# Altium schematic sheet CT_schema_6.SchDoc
size 370 x 245 mm
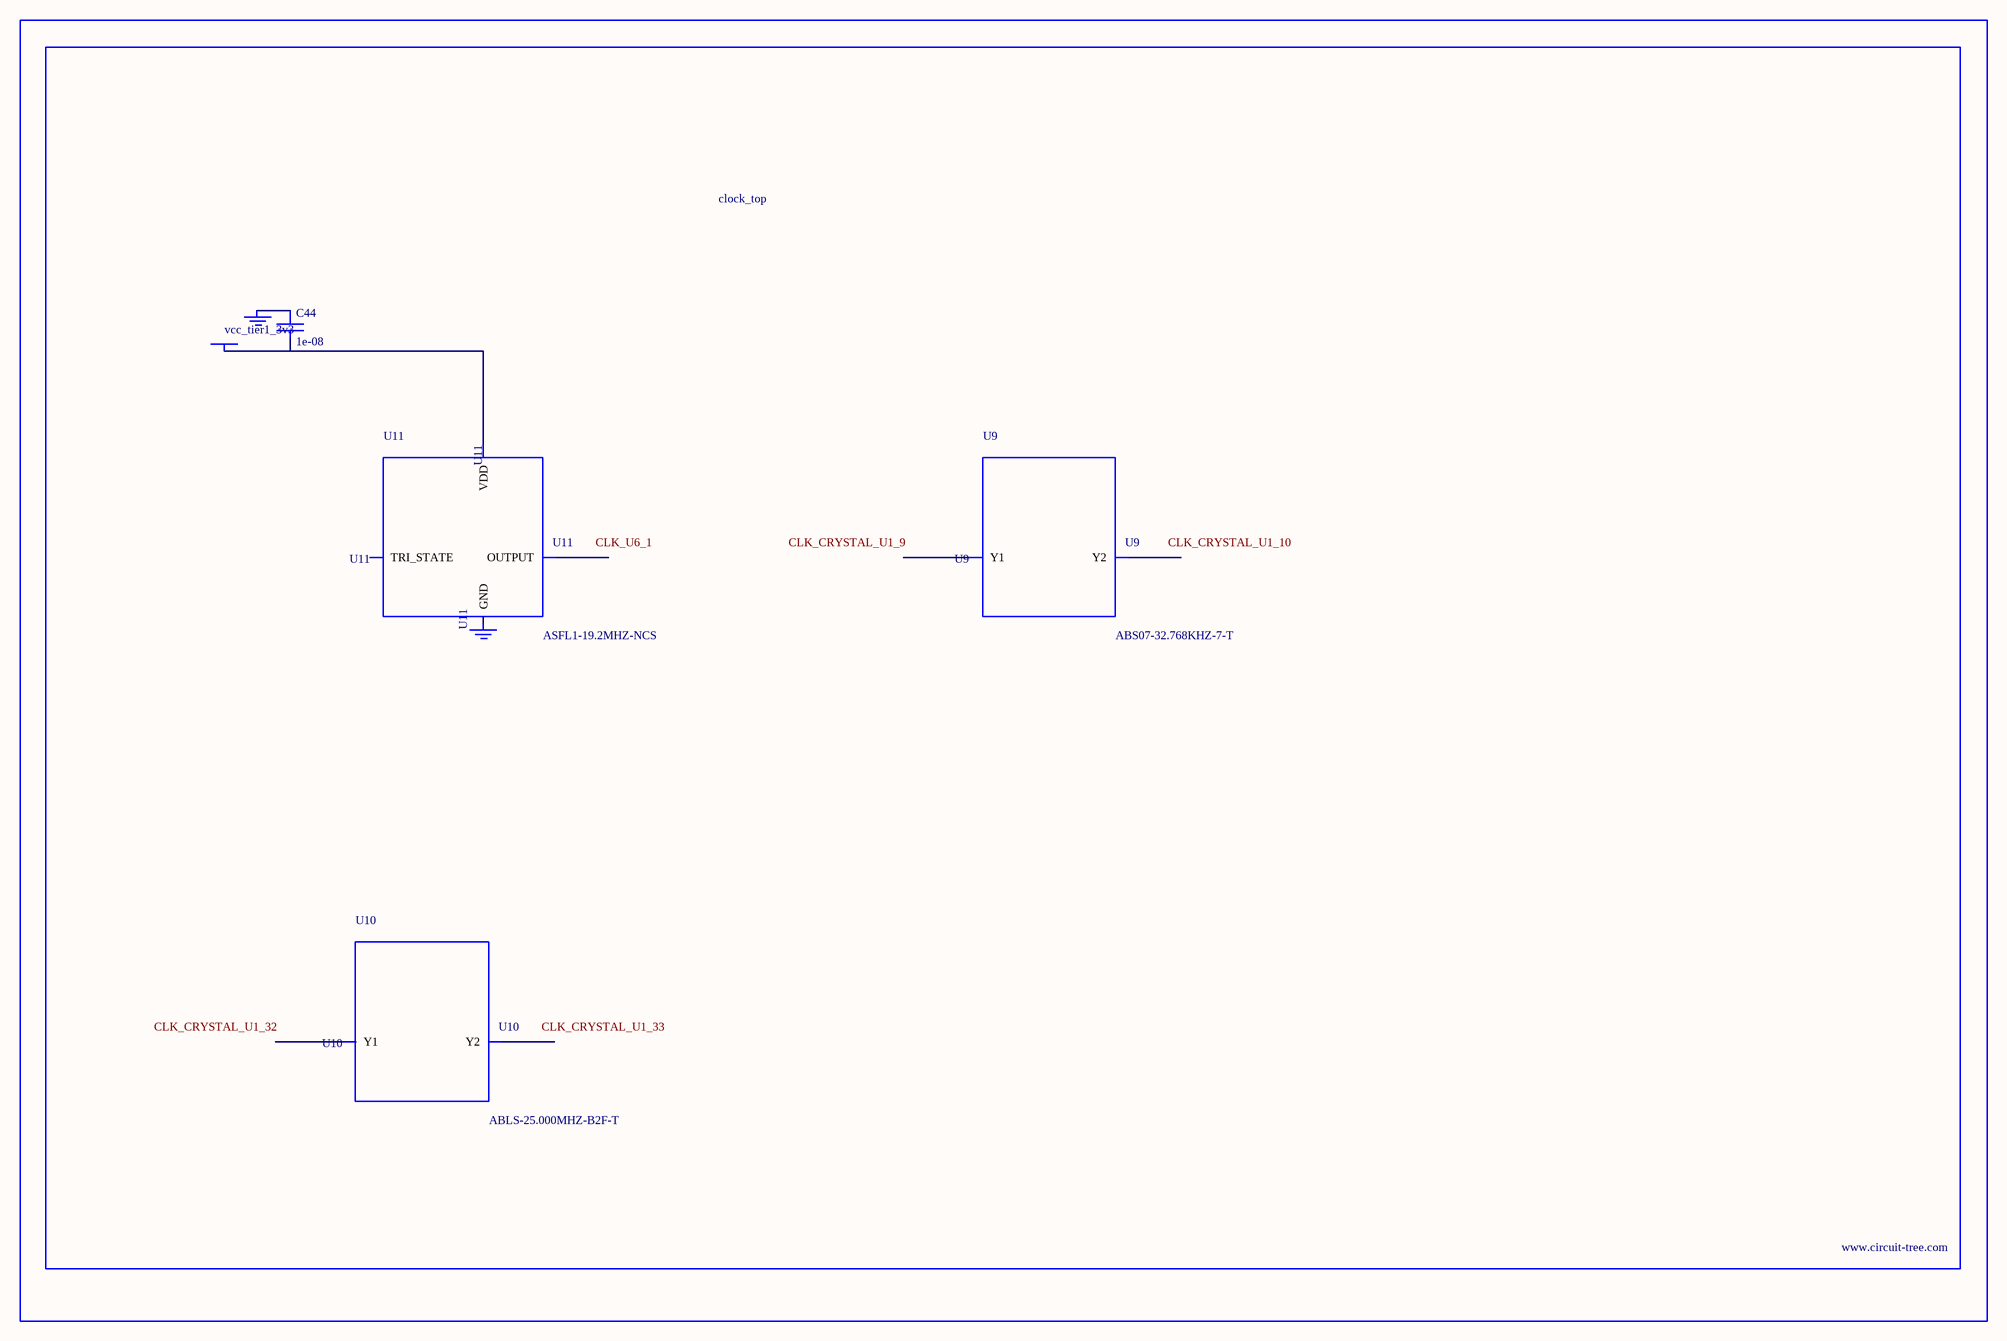
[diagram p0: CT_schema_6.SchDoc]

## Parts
BORDER5  (no value)
C44  1e-08  [C0402]
GND_INSTANCE_5_0  (no value)
GND_INSTANCE_5_1  (no value)
POWER_INSTANCE_5_0  vcc_tier1_3v3
U9  ABS07-32.768KHZ-7-T  [ABS07-32.768KHZ-7-T]
U10  ABLS-25.000MHZ-B2F-T  [ABLS-25.000MHZ-B2F-T]
U11  ASFL1-19.2MHZ-NCS  [ASFL1]

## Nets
NetC44_1: C44.1 GND_INSTANCE_5_0.0(GND)
NetC44_2: C44.2 POWER_INSTANCE_5_0.0(PWR) U11.4(VDD)

Not connected (* = marked no-connect by the designer): GND_INSTANCE_5_1 0(GND); U9 1(Y1) 2(Y2); U10 1(Y1) 2(Y2); U11 1(TRI_STATE) 2(GND) 3(OUTPUT)

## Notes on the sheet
- Labels drawn without touching a wire or pin: CLK_CRYSTAL_U1_9, CLK_CRYSTAL_U1_10, CLK_CRYSTAL_U1_32, CLK_CRYSTAL_U1_33, CLK_U6_1

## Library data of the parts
BORDER5 = BORDER_PAGE5
C44 = C0402C103K3RAC
GND_INSTANCE_5_0 GND_INSTANCE_5_1 = GND
POWER_INSTANCE_5_0 = PWR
